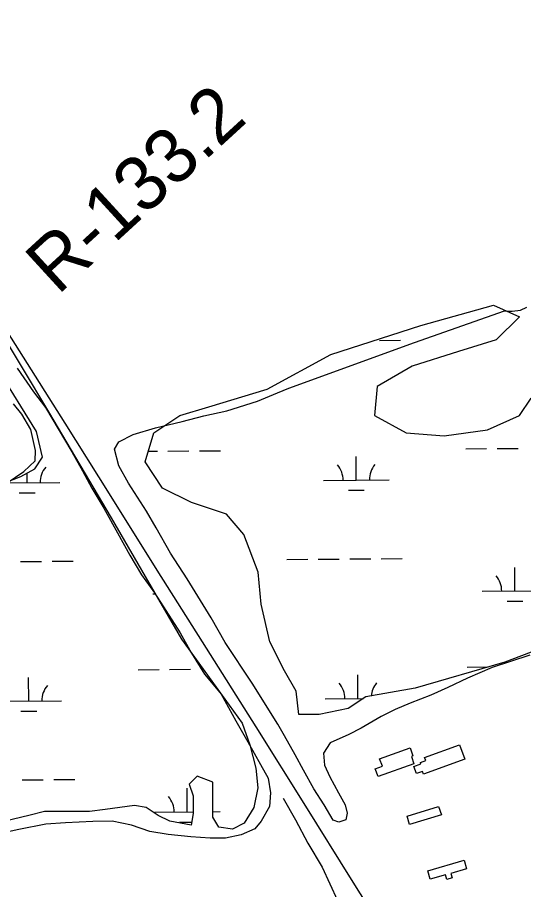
# Model space of a CAD drawing. Extents: x 3540316 to 3578335, y 553172 to 578787.
# Drawn here: x 3552978 to 3553749, y 565885 to 567214 of the extents above; entities that cross this region are included whole.
import ezdxf

# ---------------------------------------------------------------- set-up
doc = ezdxf.new("R2010")
doc.units = 0
for name, color, linetype in [('V-BLDG-OTLN', 7, 'Continuous'), ('V-RAIL-TRAK', 7, 'Continuous'), ('V-RIVR-RANG-IDEN', 7, 'Continuous'), ('V-SITE-VEGE', 7, 'Continuous'), ('V-TOPO-SHOR', 7, 'Continuous'), ('V-WETL-SWMP', 7, 'Continuous')]:
    doc.layers.add(name, color=color, linetype=linetype)

msp = doc.modelspace()

# ---------------------------------------------------------------- linework, layer by layer
at = {"layer": 'V-BLDG-OTLN'}
for points in [[(3553529.7, 566084.3), (3553576.3, 566100.6), (3553580.5, 566088.6), (3553578.3, 566087.8), (3553582.3, 566076.4), (3553527.5, 566056.9), (3553523.3, 566068.8), (3553534.2, 566072.7)], [(3553659.7, 566083.4), (3553596.8, 566060.7), (3553595.2, 566064.9), (3553586, 566061.6), (3553582.1, 566072.5), (3553592.8, 566076.3), (3553592, 566078.5), (3553600.2, 566081.5), (3553598.5, 566086.2), (3553651.5, 566105.3)], [(3553624.2, 565998.6), (3553575.6, 565983.8), (3553571.7, 565996.8), (3553619.7, 566011.4)], [(3553603.2, 565913.6), (3553658.8, 565929.6), (3553662.6, 565916.3), (3553638.7, 565909.4), (3553640.7, 565902.7), (3553632.5, 565900.3), (3553630.5, 565907.3), (3553607, 565900.5)]]:
    msp.add_lwpolyline(points, close=True, dxfattribs=at)
at = {"layer": 'V-RAIL-TRAK'}
msp.add_lwpolyline([(3552538.6, 567365.5), (3552611.3, 567269.9), (3552647.3, 567218.2), (3552692.3, 567153.4), (3552764.4, 567046.2), (3552834.1, 566938.1), (3552906.7, 566821.6), (3552980.3, 566705.8), (3553050.1, 566595.5), (3553117.5, 566487.8), (3553190.4, 566371.3), (3553259.3, 566262.5), (3553341.2, 566132.8), (3553416.9, 566012), (3553486.7, 565900.1), (3553525.1, 565838.7), (3553552.9, 565794.4)], dxfattribs=at)
at = {"layer": 'V-SITE-VEGE'}
for points in [[(3553401.2, 566090.1), (3553384.7, 566119.1), (3553374.7, 566137), (3553335.8, 566199.3), (3553294.5, 566261.1), (3553273, 566298.8), (3553236.5, 566358.2), (3553211.1, 566397.3), (3553189.1, 566435.9), (3553174.6, 566461.6), (3553147.2, 566504), (3553132.2, 566530.6), (3553126, 566555.9), (3553132.6, 566567.2), (3553154.4, 566578.2), (3553188.4, 566588.4), (3553228.7, 566598.3), (3553262.2, 566606.6), (3553297.1, 566614.4), (3553343.7, 566629.2), (3553374.2, 566641.8), (3553391.7, 566649.1), (3553582.9, 566718.7), (3553720.4, 566766.7), (3553725.7, 566766), (3553731.8, 566766.1), (3553744.7, 566767.8), (3553754.5, 566772.5)], [(3552977.3, 566679.6), (3553002.1, 566643.5), (3553020.4, 566619.6), (3553060.6, 566551.7), (3553077, 566522.9), (3553091.4, 566496.5), (3553109.7, 566465.8), (3553130.6, 566428.6), (3553149.4, 566394.4), (3553166.8, 566364.6), (3553186.6, 566336.8), (3553225.8, 566275.8), (3553243.2, 566245), (3553263, 566213.3), (3553288.2, 566182.5), (3553310.6, 566142), (3553329, 566109.8), (3553348.3, 566075.6), (3553360.2, 566054.6), (3553363.8, 566032), (3553362, 566011.4), (3553349.4, 565989.2), (3553339.7, 565977.4), (3553319.1, 565968.4), (3553295.2, 565963.4), (3553271.6, 565963.2), (3553242.2, 565965), (3553207.8, 565968.6), (3553179.8, 565973.4), (3553151.8, 565983), (3553122.3, 565989.1), (3553092.9, 565988.4), (3553051.2, 565986.7), (3553021.3, 565984.5), (3552980.2, 565976.4), (3552918.5, 565963.2)], [(3552950.6, 566497), (3552987.7, 566521.8), (3553004.8, 566538.1), (3553005.6, 566553.8), (3552998, 566586.1), (3552984.6, 566609.1), (3552971.8, 566625.2)], [(3553759.1, 566242), (3553701.4, 566223.1), (3553664.1, 566207), (3553634.1, 566192.9), (3553608, 566181.3), (3553576.5, 566168.7), (3553553.7, 566159.1), (3553532.4, 566148.5), (3553502, 566131), (3553483.1, 566121), (3553454.6, 566108.4), (3553444.5, 566092.7), (3553445.8, 566074.2), (3553453.8, 566056.8), (3553467.4, 566032.1), (3553477.4, 566014.2), (3553480.5, 566001.1), (3553478.2, 565990.9), (3553467.5, 565987.8), (3553459.2, 565990.6), (3553445.2, 566013.8), (3553429.7, 566038.4), (3553413.7, 566066.9), (3553401.2, 566090.1)]]:
    msp.add_lwpolyline(points, dxfattribs=at)
at = {"layer": 'V-TOPO-SHOR'}
msp.add_lwpolyline([(3553382.9, 566024.1), (3553401.6, 565991.3), (3553420.7, 565955.3), (3553442.1, 565919), (3553454, 565893.6), (3553477.5, 565842.8)], dxfattribs=at)
at = {"layer": 'V-WETL-SWMP'}
for p, q in [((3553529.9, 566721.6), (3553561.9, 566721.8)), ((3553177.4, 566552.7), (3553191.2, 566552.8)), ((3553207.2, 566552.9), (3553239.2, 566553.2)), ((3553255.2, 566553.3), (3553287.2, 566553.5)), ((3553661.1, 566556.4), (3553693.1, 566556.7)), ((3553709.1, 566556.8), (3553741.1, 566557)), ((3553494.4, 566508.7), (3553494.1, 566544.7)), ((3552992.5, 566504.8), (3552992.4, 566519.3)), ((3552957.8, 566504.6), (3553042.5, 566505.2)), ((3553444.4, 566508.3), (3553544.4, 566509.1)), ((3552980.6, 566489.3), (3553004.6, 566489.5)), ((3553482.5, 566493.2), (3553506.5, 566493.4)), ((3552982.6, 566384.7), (3553014.6, 566384.9)), ((3553030.6, 566385.1), (3553062.6, 566385.3)), ((3553388.5, 566387.8), (3553420.5, 566388.1)), ((3553436.5, 566388.2), (3553468.4, 566388.4)), ((3553484.4, 566388.6), (3553516.4, 566388.8)), ((3553532.4, 566388.9), (3553564.4, 566389.2)), ((3553736.1, 566339.8), (3553735.9, 566375.8)), ((3553686.2, 566339.4), (3553786.1, 566340.1)), ((3553184.3, 566335.5), (3553187.8, 566335.5)), ((3553724.3, 566324.2), (3553748.3, 566324.4)), ((3553161.7, 566219.9), (3553193.7, 566220.1)), ((3553209.7, 566220.3), (3553241.7, 566220.5)), ((3553257.7, 566220.6), (3553260.9, 566220.7)), ((3553663.6, 566223.8), (3553695.6, 566224)), ((3552995, 566172.2), (3552994.8, 566208.2)), ((3553496.9, 566176), (3553496.7, 566212)), ((3552945, 566171.8), (3553045, 566172.6)), ((3553446.9, 566175.7), (3553505.4, 566176.1)), ((3552983.2, 566156.7), (3553007.2, 566156.8)), ((3552985.1, 566052), (3553017.1, 566052.3)), ((3553033.1, 566052.4), (3553065.1, 566052.6)), ((3553236.8, 566003.2), (3553236.5, 566039.2)), ((3553186.8, 566002.8), (3553245.8, 566003.3)), ((3553275.6, 566003.5), (3553286.8, 566003.6)), ((3553224.9, 565987.7), (3553243.6, 565987.8))]:
    msp.add_line(p, q, dxfattribs=at)
for points in [[(3552863.9, 566881.1), (3553025, 566612.6), (3553120.5, 566451.5), (3553227.9, 566266.5), (3553320.4, 566138.2), (3553332.3, 566105.4), (3553341.3, 566069.6), (3553344.2, 566039.7), (3553338.3, 566009.9), (3553323.4, 565986), (3553305.5, 565977.1), (3553284.6, 565980), (3553275.6, 565995), (3553275.6, 566024.8), (3553275.6, 566048.7), (3553251.8, 566057.6), (3553239.8, 566045.7), (3553245.8, 566027.8), (3553245.8, 566000.9), (3553242.8, 565983), (3553210, 565989), (3553192.1, 565997.9), (3553174.2, 566009.9), (3553156.3, 566012.9), (3553111.5, 566006.9), (3553087.7, 566003.9), (3553019, 566003.9), (3552995.2, 565997.9), (3552920.6, 565980)], [(3552959.4, 566505.2), (3552983.2, 566514.1), (3553004.1, 566526), (3553016, 566543.9), (3553007.1, 566582.7), (3552831.1, 566866.2)], [(3553906.7, 566302.1), (3553721, 566231.4), (3553583.9, 566191.6), (3553508.7, 566178.3), (3553482.1, 566160.6), (3553437.9, 566151.7), (3553406.9, 566151.7), (3553402.5, 566187.1), (3553384.8, 566218.1), (3553362.7, 566262.3), (3553349.5, 566319.8), (3553345, 566368.5), (3553322.9, 566426), (3553296.4, 566456.9), (3553243.3, 566474.6), (3553199.1, 566496.7), (3553172.5, 566536.5), (3553185.8, 566580.7), (3553225.6, 566607.3), (3553269.8, 566620.6), (3553358.3, 566647.1), (3553455.6, 566700.2), (3553592.7, 566744.4), (3553703.3, 566775.3), (3553743.1, 566757.7), (3553707.7, 566722.3), (3553650.2, 566704.6), (3553579.4, 566682.5), (3553526.4, 566651.5), (3553521.9, 566607.3), (3553570.6, 566580.7), (3553628.1, 566576.3), (3553694.4, 566585.2), (3553743.1, 566607.3), (3553760.8, 566633.8)]]:
    msp.add_lwpolyline(points, dxfattribs=at)
for centre, start, end in [((3553047.7, 566505.7), 139.6699, 181.2135), ((3553439.1, 566508.8), 359.6699, 41.2135), ((3553549.6, 566509.6), 139.6699, 181.2135), ((3553680.9, 566339.8), 359.6699, 41.2135), ((3553050.3, 566173.1), 139.6699, 181.2135), ((3553441.7, 566176.1), 359.6699, 41.2135), ((3553552.2, 566176.9), 139.6699, 175.4207), ((3553181.6, 566003.3), 359.6699, 41.2135)]:
    msp.add_arc(centre, 35.2, start, end, dxfattribs=at)

# ---------------------------------------------------------------- texts
at = {"layer": 'V-RIVR-RANG-IDEN'}
msp.add_text('R-133.2', height=83, rotation=42.501, dxfattribs=at).set_placement((3553039.2, 566789.5))

doc.saveas('drawing.dxf')
